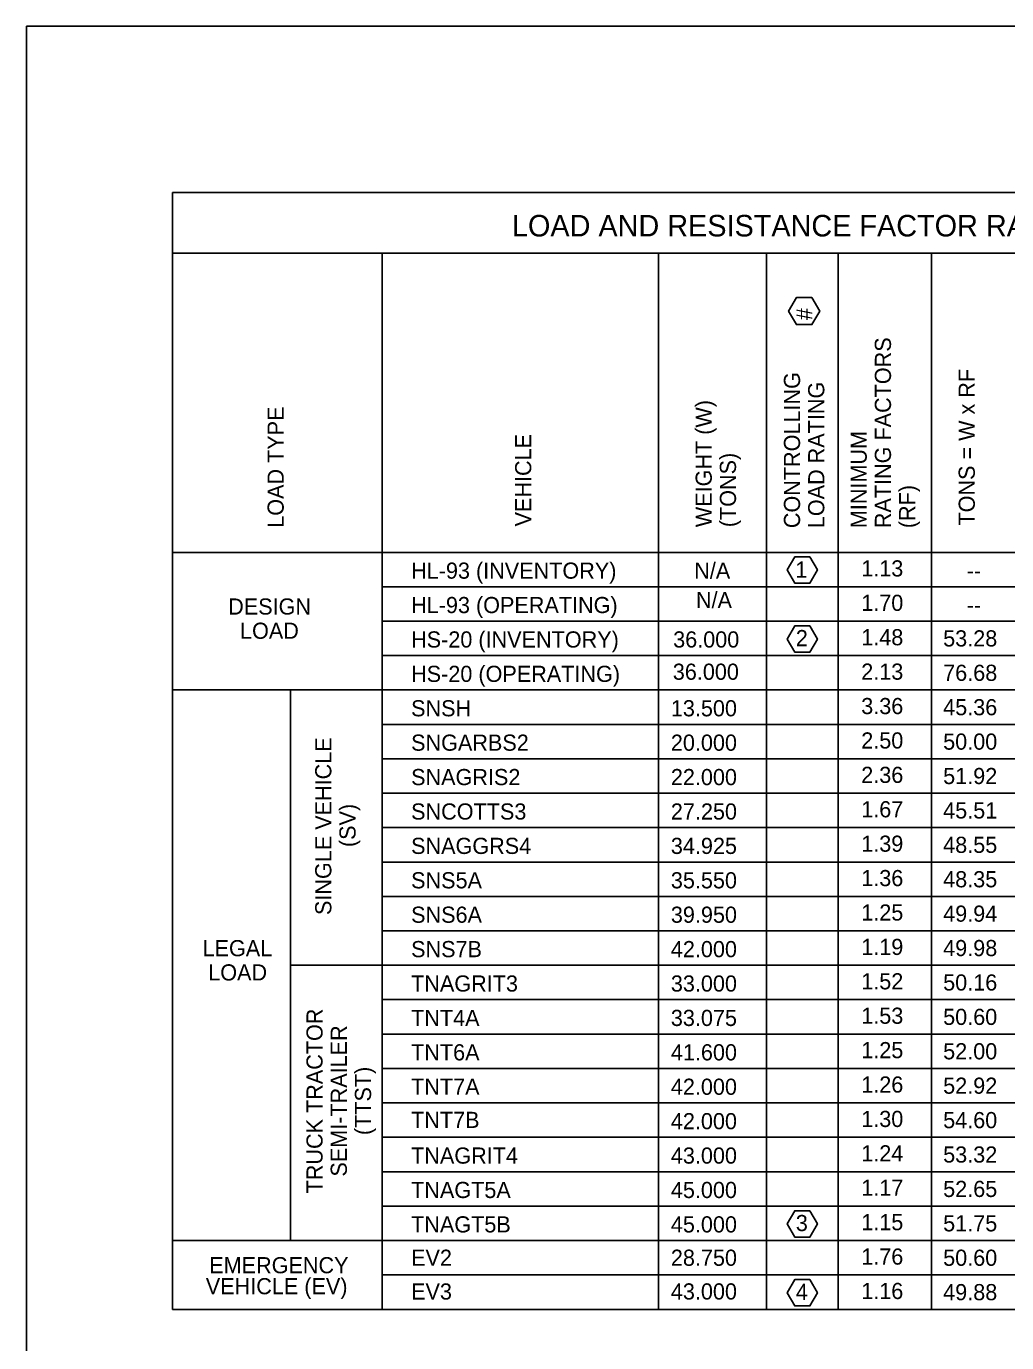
# Model space of a CAD drawing. Extents: x 0.06 to 2.81, y -0.16 to 1.8.
# Drawn here: x 0.061 to 0.789, y 0.818 to 1.796 of the extents above; entities that cross this region are included whole.
import ezdxf

# ---------------------------------------------------------------- set-up
doc = ezdxf.new("R2010")
doc.units = 0
for name, color, linetype in [('Arrowhead Terminators CELL', 7, 'Continuous'), ('Auto Dimensioning', 7, 'Continuous'), ('Dimension Lines', 7, 'Continuous'), ('Prop Horizontal Alignment', 7, 'Continuous'), ('Sheet Plot Border Inside CELL', 7, 'Continuous')]:
    doc.layers.add(name, color=color, linetype=linetype)

msp = doc.modelspace()

# ---------------------------------------------------------------- linework, layer by layer
at = {"layer": 'Auto Dimensioning'}
for p, q in [((0.16939, 1.67233), (1.82924, 1.67233)), ((0.16939, 1.67233), (0.16939, 0.84272)), ((0.16939, 1.62723), (1.82924, 1.62723)), ((0.32496, 1.62723), (0.32496, 0.84272)), ((0.53005, 1.62723), (0.53005, 0.84272)), ((0.61041, 1.62723), (0.61041, 0.84272)), ((0.66361, 1.62723), (0.66361, 0.84272)), ((0.73287, 1.62723), (0.73287, 0.84272)), ((0.16939, 1.40505), (1.82924, 1.40505)), ((0.32496, 1.37949), (1.82924, 1.37949)), ((0.32496, 1.35393), (1.82924, 1.35393)), ((0.32496, 1.32837), (1.82924, 1.32837)), ((0.16939, 1.30281), (1.82924, 1.30281)), ((0.25677, 1.30281), (0.25677, 0.89384)), ((0.32496, 1.27725), (1.82924, 1.27725)), ((0.32496, 1.25169), (1.82924, 1.25169)), ((0.32496, 1.22613), (1.82924, 1.22613)), ((0.32496, 1.20057), (1.82924, 1.20057)), ((0.32496, 1.17501), (1.82924, 1.17501)), ((0.32496, 1.14945), (1.82924, 1.14945)), ((0.32496, 1.12389), (1.82924, 1.12389)), ((0.25677, 1.09833), (1.82924, 1.09833)), ((0.32496, 1.07277), (1.82924, 1.07277)), ((0.32496, 1.04721), (1.82924, 1.04721)), ((0.32496, 1.02165), (1.82924, 1.02165)), ((0.32496, 0.99609), (1.82924, 0.99609)), ((0.32496, 0.97052), (1.82924, 0.97052)), ((0.32496, 0.94496), (1.82924, 0.94496)), ((0.32496, 0.9194), (1.82924, 0.9194)), ((0.16939, 0.89384), (1.82924, 0.89384)), ((0.32496, 0.86828), (1.82924, 0.86828)), ((0.16939, 0.84272), (1.82924, 0.84272))]:
    msp.add_line(p, q, dxfattribs=at)
for points in [[(0.64403, 1.59428), (0.63246, 1.59428), (0.62667, 1.58426), (0.63246, 1.57423), (0.64403, 1.57423), (0.64982, 1.58426)], [(0.64249, 1.40173), (0.63124, 1.40173), (0.62562, 1.39198), (0.63124, 1.38224), (0.64249, 1.38224), (0.64812, 1.39198)], [(0.64249, 1.35044), (0.63124, 1.35044), (0.62562, 1.34069), (0.63124, 1.33095), (0.64249, 1.33095), (0.64812, 1.34069)], [(0.64249, 0.91591), (0.63124, 0.91591), (0.62562, 0.90616), (0.63124, 0.89642), (0.64249, 0.89642), (0.64812, 0.90616)], [(0.64249, 0.86478), (0.63124, 0.86478), (0.62562, 0.85504), (0.63124, 0.8453), (0.64249, 0.8453), (0.64812, 0.85504)]]:
    msp.add_lwpolyline(points, close=True, dxfattribs=at)
at = {"layer": 'Prop Horizontal Alignment'}
for p, q in [((0.7332, 1.34573), (0.7332, 1.34573)), ((0.7332, 1.32249), (0.7332, 1.32249)), ((0.7332, 1.29925), (0.7332, 1.29925)), ((0.7332, 1.27601), (0.7332, 1.27601)), ((0.7332, 1.25278), (0.7332, 1.25278)), ((0.7332, 1.22954), (0.7332, 1.22954)), ((0.7332, 1.2063), (0.7332, 1.2063)), ((0.7332, 1.18307), (0.7332, 1.18307)), ((0.7332, 1.15983), (0.7332, 1.15983)), ((0.7332, 1.13659), (0.7332, 1.13659)), ((0.7332, 1.11336), (0.7332, 1.11336)), ((0.7332, 1.09012), (0.7332, 1.09012)), ((0.7332, 1.06688), (0.7332, 1.06688)), ((0.7332, 1.04365), (0.7332, 1.04365)), ((0.7332, 1.02041), (0.7332, 1.02041)), ((0.7332, 0.99717), (0.7332, 0.99717)), ((0.7332, 0.97394), (0.7332, 0.97394)), ((0.7332, 0.9507), (0.7332, 0.9507))]:
    msp.add_line(p, q, dxfattribs=at)
at = {"layer": 'Sheet Plot Border Inside CELL'}
for p in [(0.06075, 0.03753), (2.81079, 1.79583)]:
    msp.add_line(p, (0.06079, 1.79583), dxfattribs=at)

# ---------------------------------------------------------------- texts
at = {"layer": 'Arrowhead Terminators CELL'}
for s, p in [('#', (0.64428, 1.57761)), ('RATING FACTORS', (0.70273, 1.42303)), ('CONTROLLING', (0.63522, 1.42303)), ('TONS = W x RF', (0.76496, 1.42499)), ('LOAD RATING', (0.65322, 1.42303)), ('WEIGHT (W)', (0.56967, 1.42375)), ('LOAD TYPE', (0.25184, 1.42334)), ('VEHICLE', (0.43565, 1.42433)), ('MINIMUM', (0.68473, 1.42303)), ('(TONS)', (0.58767, 1.42375)), ('(RF)', (0.72073, 1.42303)), ('SINGLE VEHICLE', (0.28722, 1.13564)), ('(SV)', (0.30522, 1.18613)), ('TRUCK TRACTOR ', (0.28072, 0.92886)), ('SEMI-TRAILER ', (0.29872, 0.94135)), ('(TTST)', (0.31672, 0.97215))]:
    msp.add_text(s, height=0.012, rotation=90, dxfattribs=at).set_placement(p)
for s, p in [('1.13', (0.68063, 1.38714)), ('HL-93 (INVENTORY)', (0.34642, 1.38549)), ('N/A', (0.55662, 1.38549)), ('1', (0.63169, 1.38627)), ('--', (0.75893, 1.38549)), ('DESIGN', (0.2106, 1.35884)), ('HL-93 (OPERATING)', (0.34642, 1.35993)), ('N/A', (0.55792, 1.36363)), ('1.70', (0.68063, 1.36158)), ('--', (0.75893, 1.35993)), ('LOAD', (0.21941, 1.34084)), ('HS-20 (INVENTORY)', (0.34642, 1.33437)), ('36.000', (0.541, 1.33437)), ('2', (0.63208, 1.33537)), ('1.48', (0.68063, 1.33602)), ('53.28', (0.74146, 1.33515)), ('HS-20 (OPERATING)', (0.34642, 1.30881)), ('36.000', (0.54073, 1.31039)), ('2.13', (0.68063, 1.31046)), ('76.68', (0.74146, 1.30959)), ('SNSH', (0.34642, 1.28325)), ('13.500', (0.53929, 1.28325)), ('3.36', (0.68063, 1.2849)), ('45.36', (0.74146, 1.28403)), ('2.50', (0.68063, 1.25934)), ('SNGARBS2', (0.34642, 1.25769)), ('20.000', (0.53929, 1.25769)), ('50.00', (0.74146, 1.25847)), ('SNAGRIS2', (0.34642, 1.23213)), ('22.000', (0.53929, 1.23213)), ('2.36', (0.68063, 1.23377)), ('51.92', (0.74146, 1.23291)), ('SNCOTTS3', (0.34642, 1.20657)), ('27.250', (0.53929, 1.20657)), ('1.67', (0.68063, 1.20821)), ('45.51', (0.74146, 1.20735)), ('SNAGGRS4', (0.34642, 1.18101)), ('34.925', (0.53929, 1.18101)), ('1.39', (0.68063, 1.18265)), ('48.55', (0.74146, 1.18179)), ('SNS5A', (0.34642, 1.15545)), ('35.550', (0.53929, 1.15545)), ('1.36', (0.68063, 1.15709)), ('48.35', (0.74146, 1.15623)), ('SNS6A', (0.34642, 1.12989)), ('39.950', (0.53929, 1.12989)), ('1.25', (0.68063, 1.13153)), ('49.94', (0.74146, 1.13067)), ('LEGAL', (0.19157, 1.10502)), ('SNS7B', (0.34642, 1.10433)), ('42.000', (0.53929, 1.10433)), ('1.19', (0.68063, 1.10597)), ('49.98', (0.74146, 1.10511)), ('LOAD', (0.1958, 1.08702)), ('TNAGRIT3', (0.34642, 1.07877)), ('33.000', (0.53929, 1.07877)), ('1.52', (0.68063, 1.08041)), ('50.16', (0.74146, 1.07955)), ('1.53', (0.68063, 1.05485)), ('50.60', (0.74146, 1.05399)), ('TNT4A', (0.34642, 1.05321)), ('33.075', (0.53929, 1.05321)), ('TNT6A', (0.34642, 1.02765)), ('41.600', (0.53929, 1.02765)), ('1.25', (0.68063, 1.02929)), ('52.00', (0.74146, 1.02843)), ('TNT7A', (0.34642, 1.00209)), ('42.000', (0.53929, 1.00209)), ('1.26', (0.68063, 1.00373)), ('52.92', (0.74146, 1.00287)), ('TNT7B', (0.34642, 0.97745)), ('42.000', (0.53929, 0.97652)), ('1.30', (0.68063, 0.97817)), ('54.60', (0.74146, 0.9773)), ('TNAGRIT4', (0.34642, 0.95096)), ('43.000', (0.53929, 0.95096)), ('1.24', (0.68063, 0.95261)), ('53.32', (0.74146, 0.95174)), ('1.17', (0.68063, 0.92705)), ('TNAGT5A', (0.34642, 0.9254)), ('45.000', (0.53929, 0.9254)), ('52.65', (0.74146, 0.92618)), ('TNAGT5B', (0.34642, 0.89984)), ('45.000', (0.53929, 0.89984)), ('3', (0.63208, 0.90084)), ('1.15', (0.68063, 0.90149)), ('51.75', (0.74146, 0.90062)), ('EMERGENCY ', (0.19654, 0.86951)), ('EV2', (0.34642, 0.87507)), ('28.750', (0.53929, 0.87507)), ('1.76', (0.68063, 0.87593)), ('50.60', (0.74146, 0.87506)), ('VEHICLE (EV)', (0.194, 0.85391)), ('EV3', (0.34642, 0.84999)), ('43.000', (0.53929, 0.85003)), ('4', (0.63208, 0.84972)), ('1.16', (0.68063, 0.85037)), ('49.88', (0.74146, 0.8495))]:
    msp.add_text(s, height=0.012, dxfattribs=at).set_placement(p)
at = {"layer": 'Dimension Lines'}
msp.add_text('LOAD AND RESISTANCE FACTOR RATING (LRFR) SUMMARY FOR PRESTRESSED CONCRETE GIRDERS', height=0.016, dxfattribs=at).set_placement((0.4213, 1.63973))

doc.saveas('drawing.dxf')
